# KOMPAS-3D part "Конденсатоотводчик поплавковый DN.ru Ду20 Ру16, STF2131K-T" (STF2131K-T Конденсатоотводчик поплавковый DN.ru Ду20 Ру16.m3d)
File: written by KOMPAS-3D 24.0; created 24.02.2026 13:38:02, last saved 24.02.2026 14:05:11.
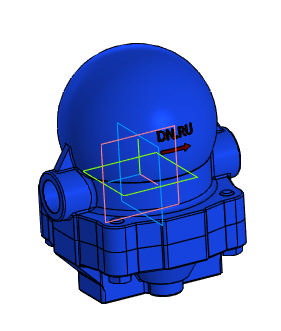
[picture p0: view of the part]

Document properties: Автор: R2D2; Полное имя файла: ..\DN15\STF2131K-T Конденсатоотводчик поплавковый DN.ru Ду15 Ру16.cdw

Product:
- Part/product: Конденсатоотводчик поплавковый DN.ru Ду20 Ру16  | designation STF2131K-T
    Масса: 2.8
    Раздел спецификации: Прочие изделия
    Форматы листов документа: A2
    Примечание: D150-00320
    additional columns: D150-00320

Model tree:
1. Операция без истории:2

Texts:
  STF2131K-T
